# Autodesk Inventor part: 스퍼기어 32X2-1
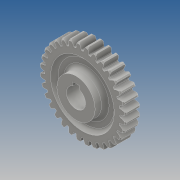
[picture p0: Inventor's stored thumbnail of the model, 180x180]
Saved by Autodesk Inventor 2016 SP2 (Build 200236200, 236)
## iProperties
Created: 2018-07
Part Number: 스퍼기어 32X2-1
Material: Generic
Document SubType Name: Modeling
Designer: Administrator
Density: 1 g/cm^3
Appearance: Default
Author: Administrator
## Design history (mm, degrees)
sketch "스케치1"
  geometry: L1 (-11, 0)-(11, 0); L2 (-11, 0)-(-11, 7.5); L3 (-11, 15)-(-3, 15); L4 (-3, 15)-(-3, 25); L5 (-3, 25)-(-6, 25); L6 (-6, 25)-(-6, 34); L7 (-6, 34)-(6, 34); L8 (6, 34)-(6, 25); L9 (6, 25)-(3, 25); L10 (3, 25)-(3, 15); L11 (3, 15)-(11, 15); L12 (11, 15)-(11, 7.5); L13 (-11, 7.5)-(11, 7.5); L14 (-11, 7.5)-(-11, 15); L15 (11, 7.5)-(11, 0); 3 further points
  constraints: 30 end point, 10 perpendicular, 4 point on line, 2 horizontal, 2 midpoint, 2 vertical, 1 coincident, 1 collinear, 1 vertical alignment
  dimensions: "d0" = 22 distance of L1.start L1.end; "d1" = 15 distance of L1.start L3.start; "d2" = 12 distance of L6.end L7.end; "d3" = 6 distance between parallel lines of L4 L10; "d4" = 50 diameter of L9 L1; "d5" = 68 diameter of L7 L1; "d6" = 15 diameter of L13 L1
revolve "회전1" sketch "스케치1" stored, may be unused: angle "d7" = 90 deg
sketch "스케치3"
  geometry: L1 (-2.5, 9.8)-(2.5, 9.8); L2 (2.5, 9.8)-(2.5, 7.071); L3 (-2.5, 7.071)-(-2.5, 9.8); A1 r 7.5 centre (0, 0) between (2.5, 7.071) and (-2.5, 7.071) reference
  constraints: 6 end point, 2 parallel, 2 point on circle, 1 horizontal, 1 perpendicular
  dimensions: "d23" = 5 distance of L1.start L1.end; "d24" = 2.3 distance edge to line of A1 L1
extrude "돌출2" cut sketch "스케치3" stored distance "d25" = 12; taper "d26" = 0 deg
sketch "스케치4"
  geometry: L1 (0, 0)-(3.349, 33.835); L2 (2.338, 29.407)-(2.781, 33.886); L3 (1.339, 29.47)-(1.585, 31.961); L4 (0.838, 29.488)-(1.085, 31.982); L5 (0, 0)-(0, 34); A1 r 34 centre (0, 0) between (3.349, 33.835) and (0, 34) reference; A2 r 34 centre (0, 0) between (3.349, 33.835) and (0, 34) reference; A3 r 32 centre (0, 0) between (1.085, 31.982) and (1.585, 31.961); A4 r 9.275 centre (10.004, 28.068) between (2.781, 33.886) and (0.838, 29.488); A5 r 9.275 centre (-10.004, 28.068) between (-0.838, 29.488) and (-2.781, 33.886); A6 r 29.5 centre (0, 0) between (0.838, 29.488) and (-0.838, 29.488); A7 r 34 centre (0, 0) between (2.781, 33.886) and (-2.781, 33.886)
  constraints: 16 point on circle, 10 end point, 5 centre point, 4 coincident, 3 parallel, 3 symmetric about line, 1 vertical, 1 other
  dimensions: "d30" = 64 diameter of A3; "d36" = 1.57 distance between parallel lines of L3 L1; "d37" = 1 distance between parallel lines of L3 L2; "d38" = 0.5 distance between parallel lines of L4 L3; "d39" = 5.652 deg angle of L5 L1
extrude "돌출3" cut sketch "스케치4" stored distance "d40" = 12; taper "d41" = 0 deg
chamfer "모따기4" distance "d55" = 1; stored, may be unused: second distance "d56" = 2, angle "d57" = 45 deg
fillet "모깎기4" dims "d58" = 0.5
fillet "모깎기5" dims "d62" = 3
node "솔리드1"
pattern_circular "원형 패턴4" dims angle "d60" = 360 deg
other parameters: "d27" = 1.57, "d28" = 1, "d29" = 0.5, "d33" = 1.57, "d34" = 1, "d35" = 0.5
